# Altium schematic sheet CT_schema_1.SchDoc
size 530 x 490 mm
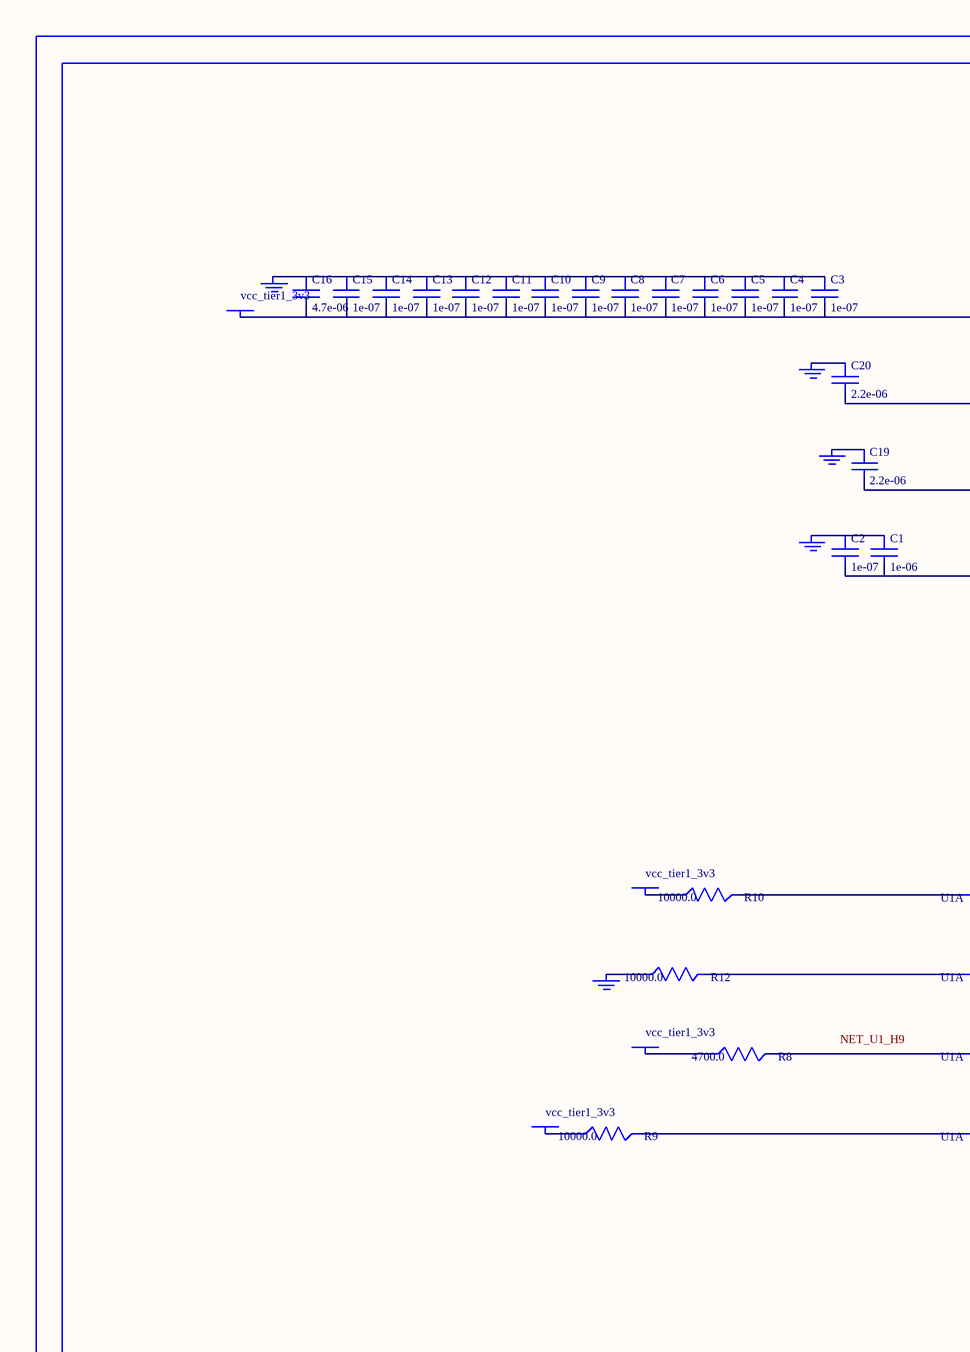
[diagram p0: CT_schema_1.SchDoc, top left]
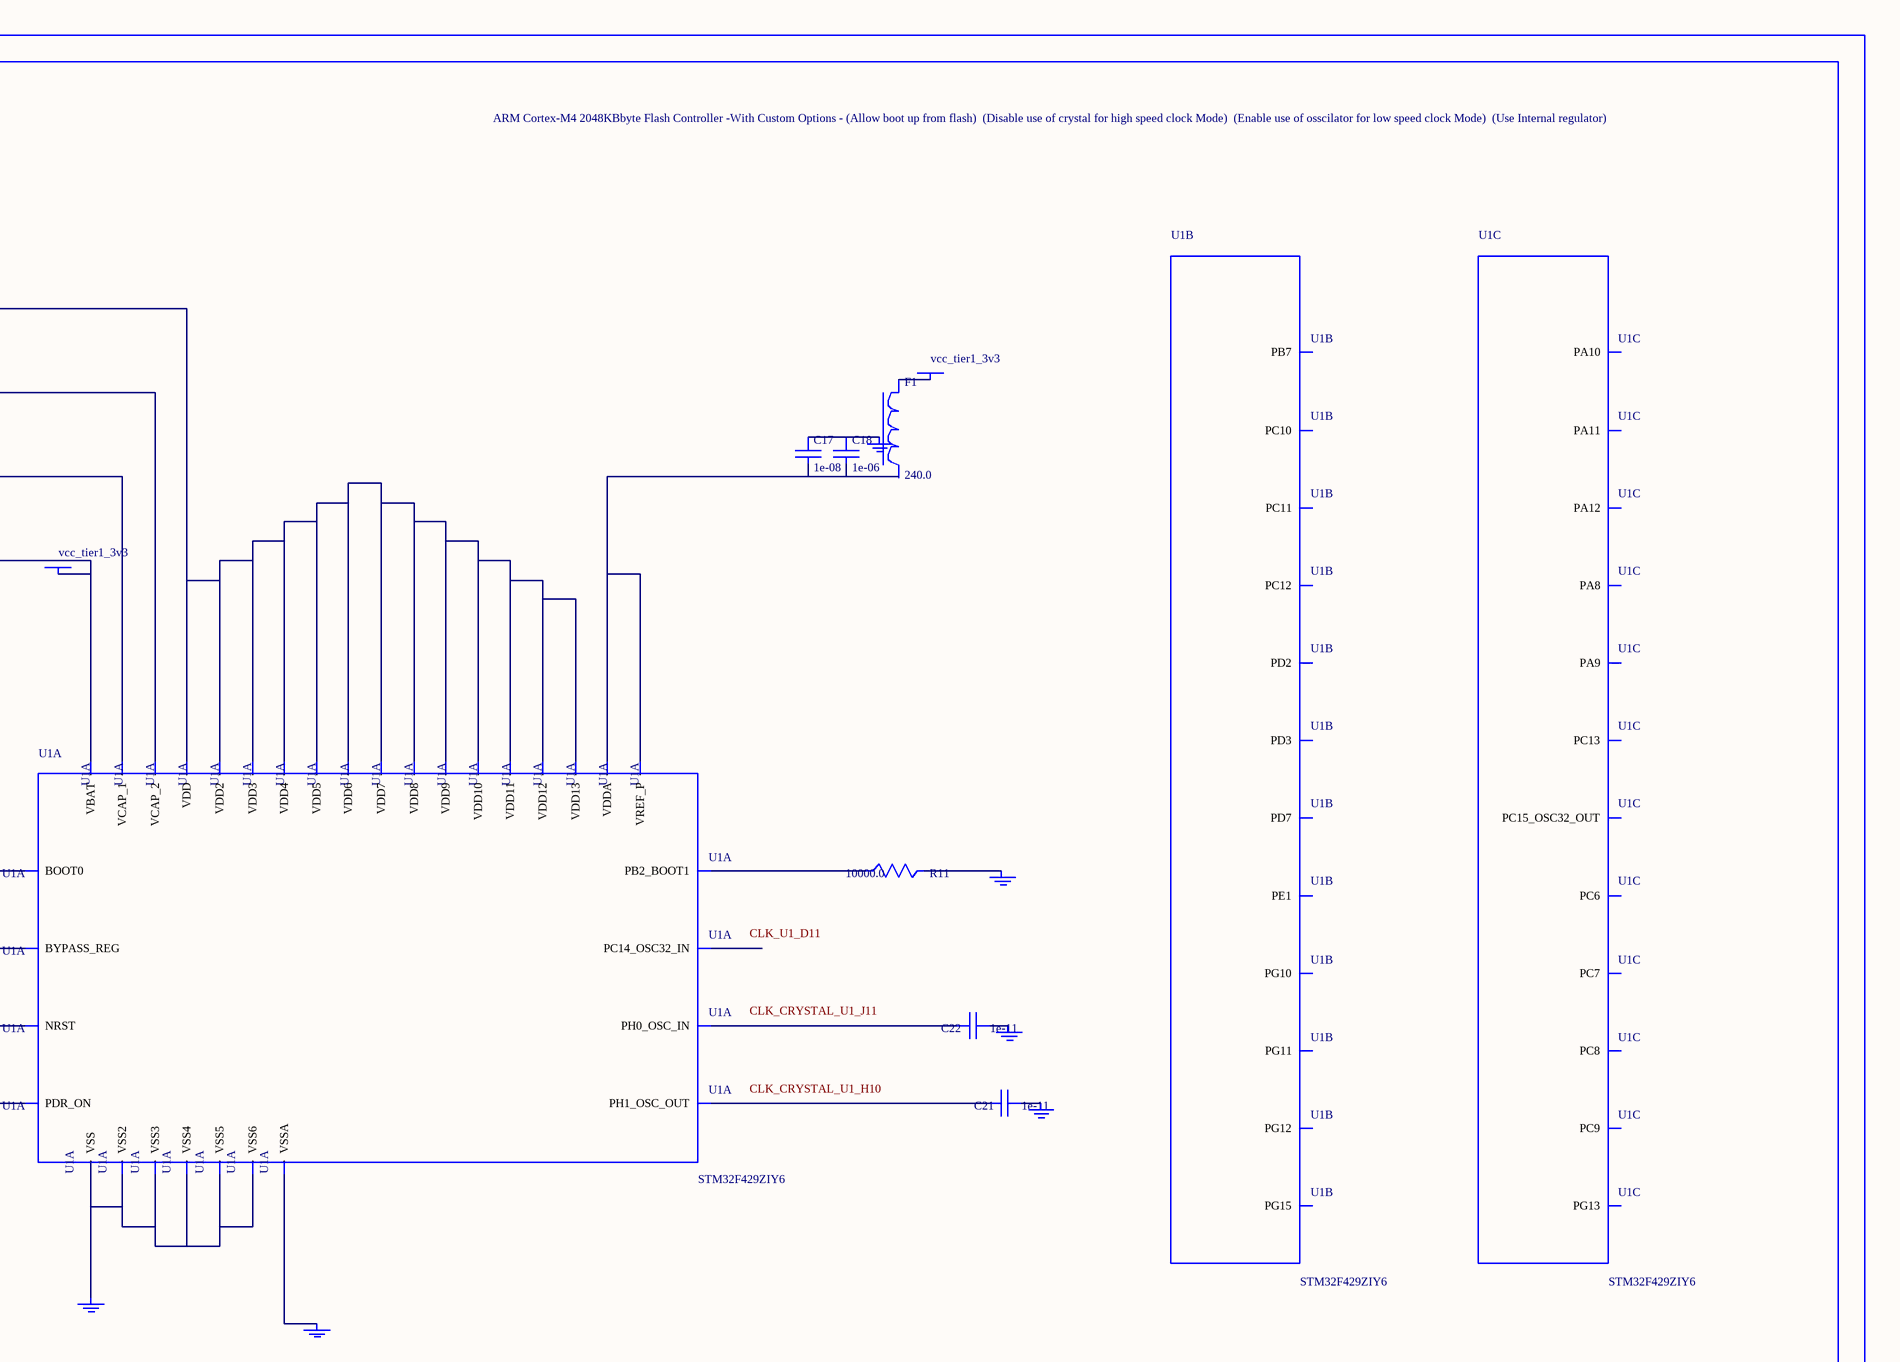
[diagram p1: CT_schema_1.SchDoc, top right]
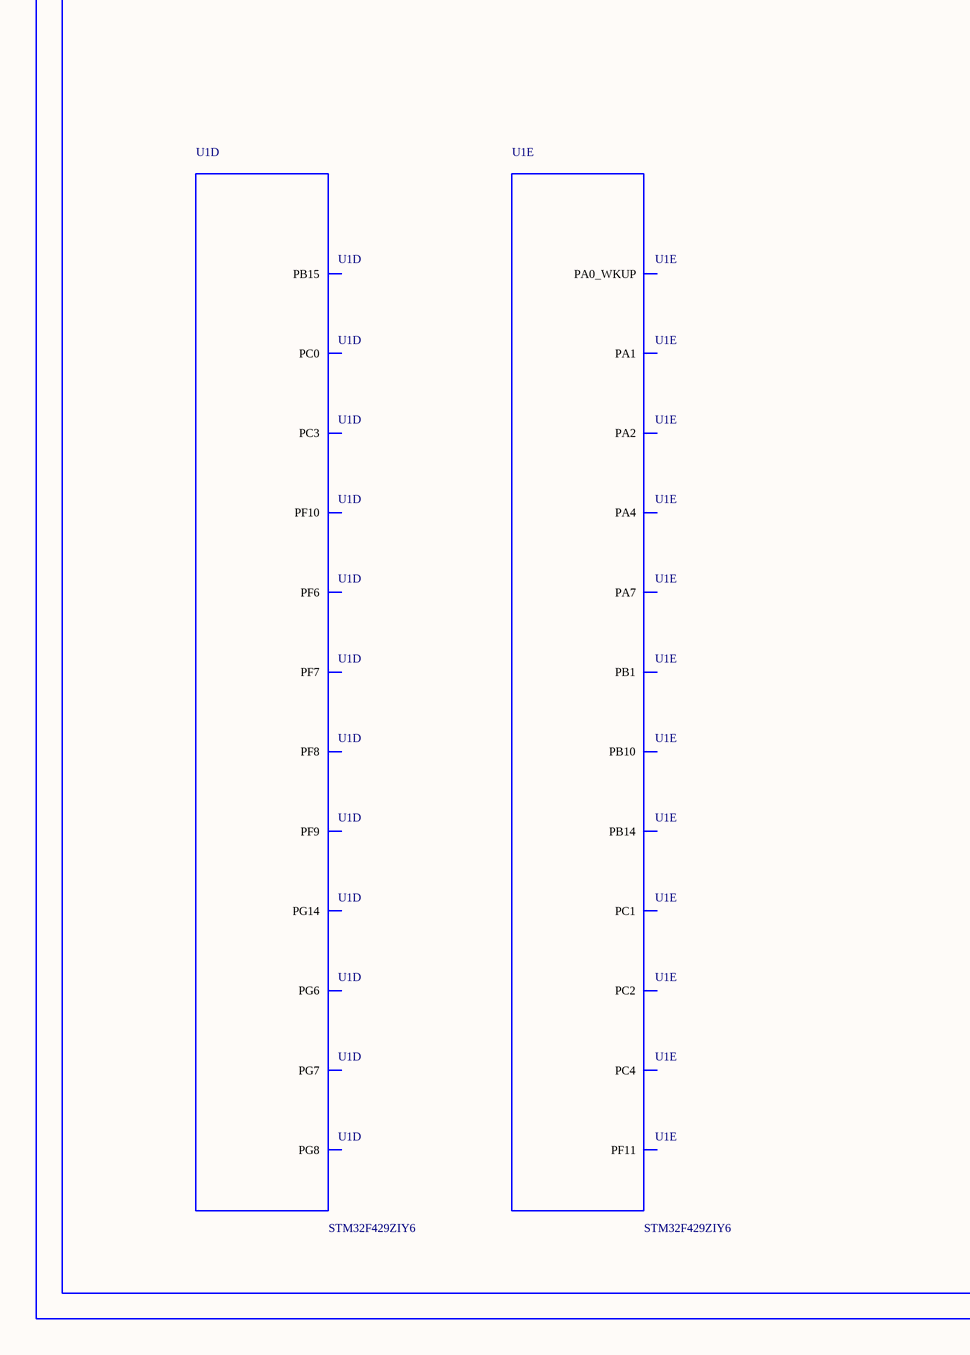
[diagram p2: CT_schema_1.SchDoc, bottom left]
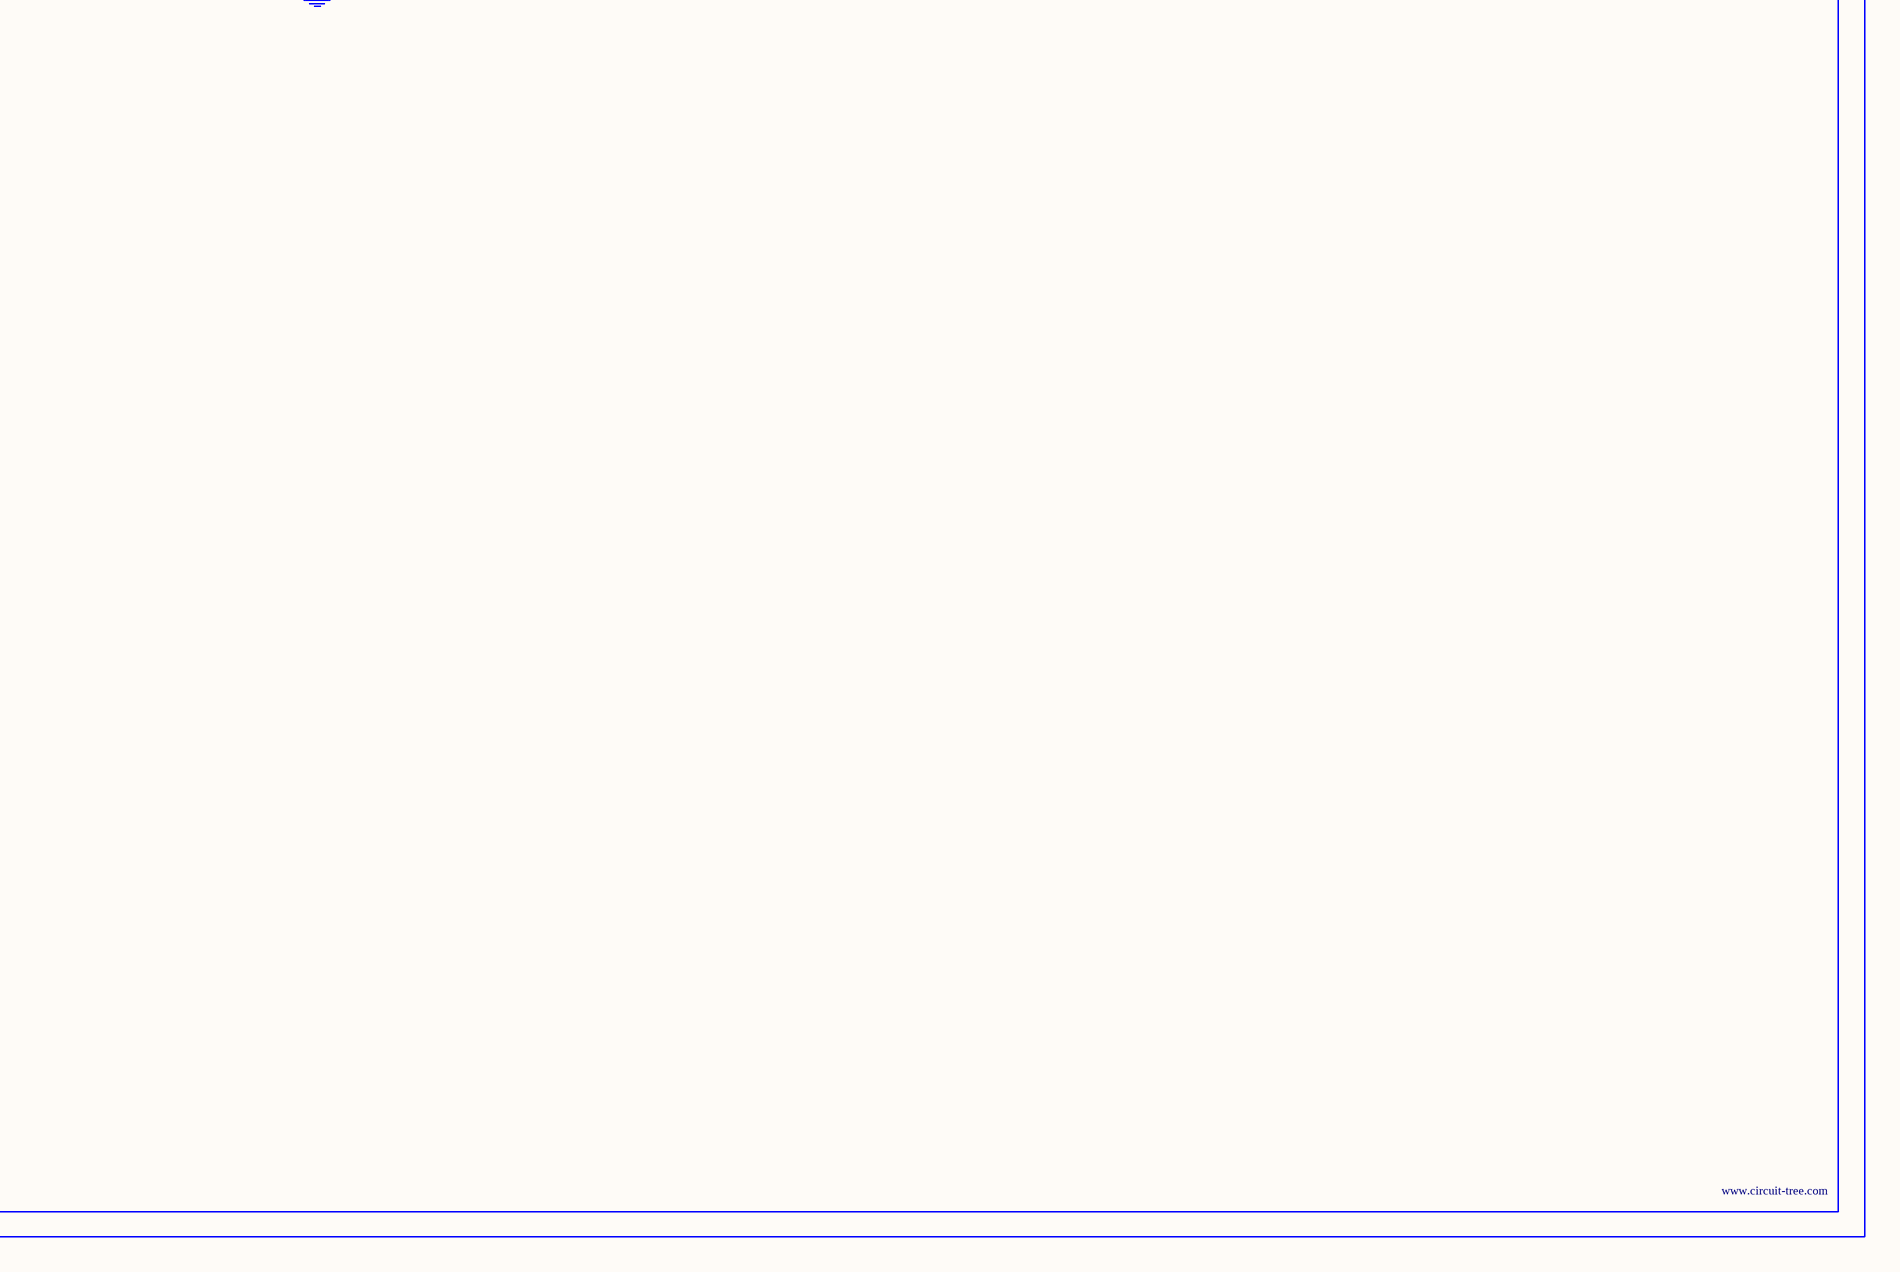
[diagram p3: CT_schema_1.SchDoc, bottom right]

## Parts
BORDER0  (no value)
C1  1e-06  [C0603]
C2  1e-07  [C0603]
C3  1e-07  [C0603]
C4  1e-07  [C0603]
C5  1e-07  [C0603]
C6  1e-07  [C0603]
C7  1e-07  [C0603]
C8  1e-07  [C0603]
C9  1e-07  [C0603]
C10  1e-07  [C0603]
C11  1e-07  [C0603]
C12  1e-07  [C0603]
C13  1e-07  [C0603]
C14  1e-07  [C0603]
C15  1e-07  [C0603]
C16  4.7e-06  [C0603]
C17  1e-08  [C0603]
C18  1e-06  [C0603]
C19  2.2e-06  [C0603]
C20  2.2e-06  [C0603]
C21  1e-11  [C0402]
C22  1e-11  [C0402]
F1  240.0  [L0603]
GND_INSTANCE_0_0  (no value)
GND_INSTANCE_0_1  (no value)
GND_INSTANCE_0_2  (no value)
GND_INSTANCE_0_3  (no value)
GND_INSTANCE_0_4  (no value)
GND_INSTANCE_0_5  (no value)
GND_INSTANCE_0_6  (no value)
GND_INSTANCE_0_7  (no value)
GND_INSTANCE_0_8  (no value)
GND_INSTANCE_0_9  (no value)
GND_INSTANCE_0_10  (no value)
POWER_INSTANCE_0_0  vcc_tier1_3v3
POWER_INSTANCE_0_1  vcc_tier1_3v3
POWER_INSTANCE_0_2  vcc_tier1_3v3
POWER_INSTANCE_0_3  vcc_tier1_3v3
POWER_INSTANCE_0_4  vcc_tier1_3v3
POWER_INSTANCE_0_5  vcc_tier1_3v3
R8  4700.0  [R0603]
R9  10000.0  [R0603]
R10  10000.0  [R0603]
R11  10000.0  [R0603]
R12  10000.0  [R0603]
U1  STM32F429ZIY6  [WLCSP143]  (parts A,B,C,D,E of 13)

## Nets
NetC1_1: C1.1 C2.1 GND_INSTANCE_0_0.0(GND)
NetC1_2: C1.2 C2.2 POWER_INSTANCE_0_0.0(PWR) U1.C11(VBAT)
NetC3_1: C3.1 C4.1 C5.1 C6.1 C7.1 C8.1 C9.1 C10.1 C11.1 C12.1 C13.1 C14.1 C15.1 C16.1 GND_INSTANCE_0_2.0(GND)
NetC3_2: C3.2 C4.2 C5.2 C6.2 C7.2 C8.2 C9.2 C10.2 C11.2 C12.2 C13.2 C14.2 C15.2 C16.2 POWER_INSTANCE_0_2.0(PWR) U1.A1(VDD) U1.C1(VDD2) U1.C5(VDD3) U1.D7(VDD4) U1.E6(VDD6) U1.E10(VDD5) U1.G1(VDD7) U1.G7(VDD8) U1.J5(VDD9) U1.J6(VDD10) U1.J7(VDD11) U1.J8(VDD12) U1.L1(VDD13)
NetC17_1: C17.1 C18.1 GND_INSTANCE_0_1.0(GND)
NetC17_2: C17.2 C18.2 U1.L10(VDDA) U1.L11(VREF_P)
NetC19_1: C19.1 GND_INSTANCE_0_5.0(GND)
NetC19_2: C19.2 U1.N2(VCAP_1)
NetC20_1: C20.1 GND_INSTANCE_0_6.0(GND)
NetC20_2: C20.2 U1.D1(VCAP_2)
NetC21_1: C21.1 GND_INSTANCE_0_7.0(GND)
NetC21_2: C21.2 U1.H10(PH1_OSC_OUT)
NetC22_1: C22.1 GND_INSTANCE_0_8.0(GND)
NetC22_2: C22.2 U1.J11(PH0_OSC_IN)
NetF1_1: F1.1 POWER_INSTANCE_0_1.0(PWR)
NetGND_INSTANCE_0_3_0: GND_INSTANCE_0_3.0(GND) R11.2
NetGND_INSTANCE_0_4_0: GND_INSTANCE_0_4.0(GND) R12.1
NetGND_INSTANCE_0_9_0: GND_INSTANCE_0_9.0(GND) U1.K10(VSSA)
NetGND_INSTANCE_0_10_0: GND_INSTANCE_0_10.0(GND) U1.D2(VSS) U1.E7(VSS2) U1.F5(VSS3) U1.H2(VSS4) U1.H3(VSS5) U1.H7(VSS6)
NetPOWER_INSTANCE_0_3_0: POWER_INSTANCE_0_3.0(PWR) R9.1
NetPOWER_INSTANCE_0_4_0: POWER_INSTANCE_0_4.0(PWR) R10.1
NetPOWER_INSTANCE_0_5_0: POWER_INSTANCE_0_5.0(PWR) R8.1
NetR8_2: R8.2 U1.H9(NRST)
NetR9_2: R9.2 U1.A11(PDR_ON)
NetR10_2: R10.2 U1.C9(BOOT0)
NetR11_1: R11.1 U1.L7(PB2_BOOT1)
NetR12_2: R12.2 U1.N11(BYPASS_REG)

Not connected (* = marked no-connect by the designer): F1 2; U1 A2(PC10) A3(PD2) A5(PD7) A6(PG12) A7(PG15) A10(PE1) B2(PC11) B4(PD3) B6(PG11) B8(PB7) C3(PC12) C6(PG10) D4(PA11) D5(PA10) D6(PG13) D10(PC13) D11(PC14_OSC32_IN) E1(PA12) E2(PA9) E3(PC9) E4(PC8) E11(PC15_OSC32_OUT) F1(PA8) F2(PC6) F3(PC7) F6(PG14) F7(PF7) G2(PG8) G4(PG6) G8(PF9) G9(PF10) G10(PF6) H1(PG7) H8(PC0) H11(PF8) J3(PB15) J9(PC3) J10(PC2) K3(PB14) K7(PB1) K8(PA1) K9(PA0_WKUP) K11(PC1) L8(PA7) L9(PA2) M3(PB10) M7(PF11) M8(PC4) M10(PA4)

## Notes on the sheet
- Labels drawn without touching a wire or pin: CLK_CRYSTAL_U1_H10, CLK_CRYSTAL_U1_J11, CLK_U1_D11, NET_U1_H9

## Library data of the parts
BORDER0 = BORDER_PAGE0
C1 C18 = C0603C105K3RACTU
C2-C15 = 06035C104K4Z2A
C16 = GRM188R6YA475KE15D
C17 = 06035C103K4Z2A
C19 C20 = C0603C225K8RACTU
C21 C22 = C0402C100K3GACTU
F1 = Z0603C241ASMST
GND_INSTANCE_0_0-GND_INSTANCE_0_10 = GND
POWER_INSTANCE_0_0-POWER_INSTANCE_0_5 = PWR
R8 = RC0603JR-074K7L
R9-R12 = RC0603JR-0710KL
